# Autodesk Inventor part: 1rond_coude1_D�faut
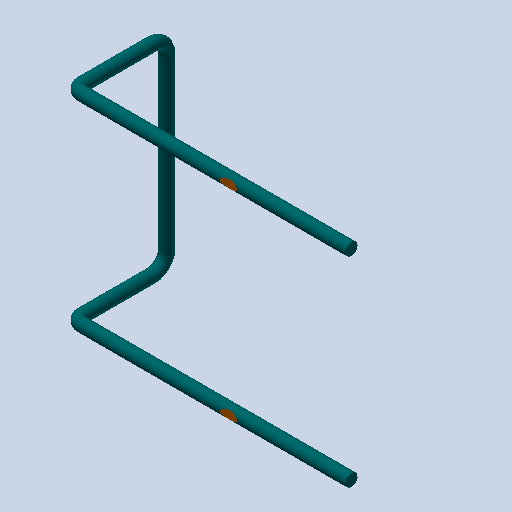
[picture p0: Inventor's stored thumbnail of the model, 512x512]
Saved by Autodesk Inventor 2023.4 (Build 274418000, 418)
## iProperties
Created: 2011-01
Part Number: 1rond_coude1_D�faut
Document SubType Name: Modeling
Designer: eric
Density: 1 g/cm^3
Mass: 29.987 g
Surface Area: 151.044 cm^2
Volume: 29.987 cm^3
Material: Générique
Appearance: 255,128,0
Author: eric
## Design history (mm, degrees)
feature "Base1"
node "Corps solides"
node "Corps surfaciques"
node "Solide1"
